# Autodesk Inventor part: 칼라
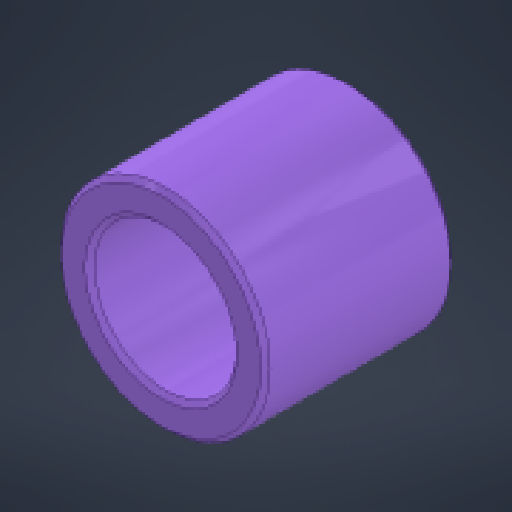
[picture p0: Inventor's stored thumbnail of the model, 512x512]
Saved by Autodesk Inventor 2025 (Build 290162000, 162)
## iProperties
Created: 2025-08
Part Number: 칼라
Material: 스테인리스강
Document SubType Name: Modeling
Designer: infra023
Density: 8.08 g/cm^3
Appearance: 기본값
Author: jhkim
Sending System: Autodesk Inventor 2026
Preprocessor: ST-DEVELOPER v20.1
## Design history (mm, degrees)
feature "솔리드1"
node "솔리드2"
